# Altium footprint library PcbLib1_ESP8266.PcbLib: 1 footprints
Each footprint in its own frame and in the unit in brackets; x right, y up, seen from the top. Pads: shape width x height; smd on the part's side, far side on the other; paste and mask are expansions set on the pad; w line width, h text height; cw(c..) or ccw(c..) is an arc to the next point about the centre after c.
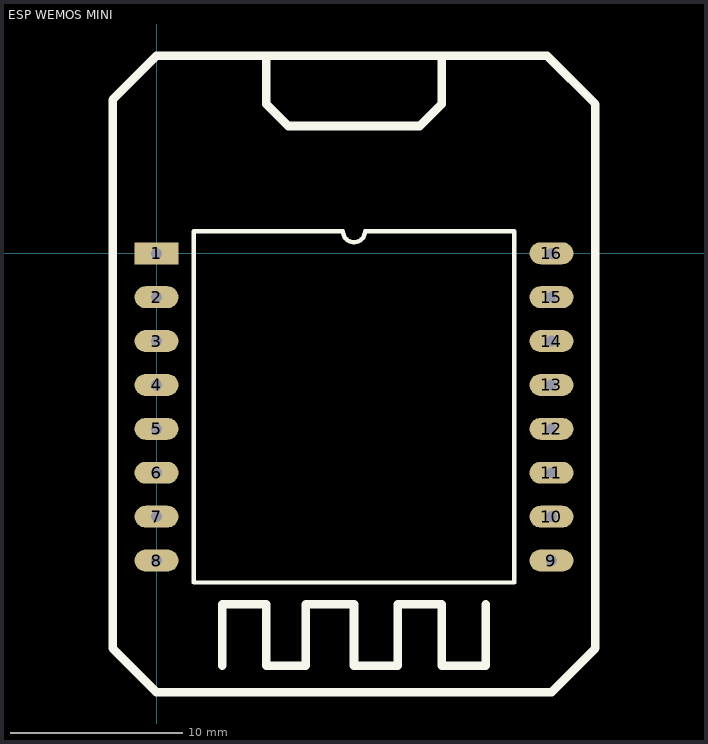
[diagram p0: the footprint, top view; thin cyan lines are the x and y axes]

## ESP WEMOS MINI [mil]
pads (16):
  rect 100x50 hole 25: 1(0,0)
  oval 100x50 hole 25: 2(0,-100) 3(0,-200) 4(0,-300) 5(0,-400) 6(0,-500) 7(0,-600) 8(0,-700) 9(900,-700) 10(900,-600) 11(900,-500) 12(900,-400) 13(900,-300) 14(900,-200) 15(900,-100) 16(900,0)
Top Overlay:
  lines w10: 85,-750 85,50 425,50 ccw(c450,50) 475,50 815,50 815,-750 85,-750
  lines w19.68: 150,-940 150,-800 250,-800 250,-940 340,-940 340,-800 450,-800 450,-940 550,-940 550,-810 550,-800 650,-800 650,-940 750,-940 750,-800 ; 250,440 250,340 300,290 600,290 650,340 650,440 ; -100,-900 0,-1000 900,-1000 1000,-900 1000,340 890,450 0,450 -100,350 -100,-900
